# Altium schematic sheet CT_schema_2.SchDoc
size 384 x 228 mm
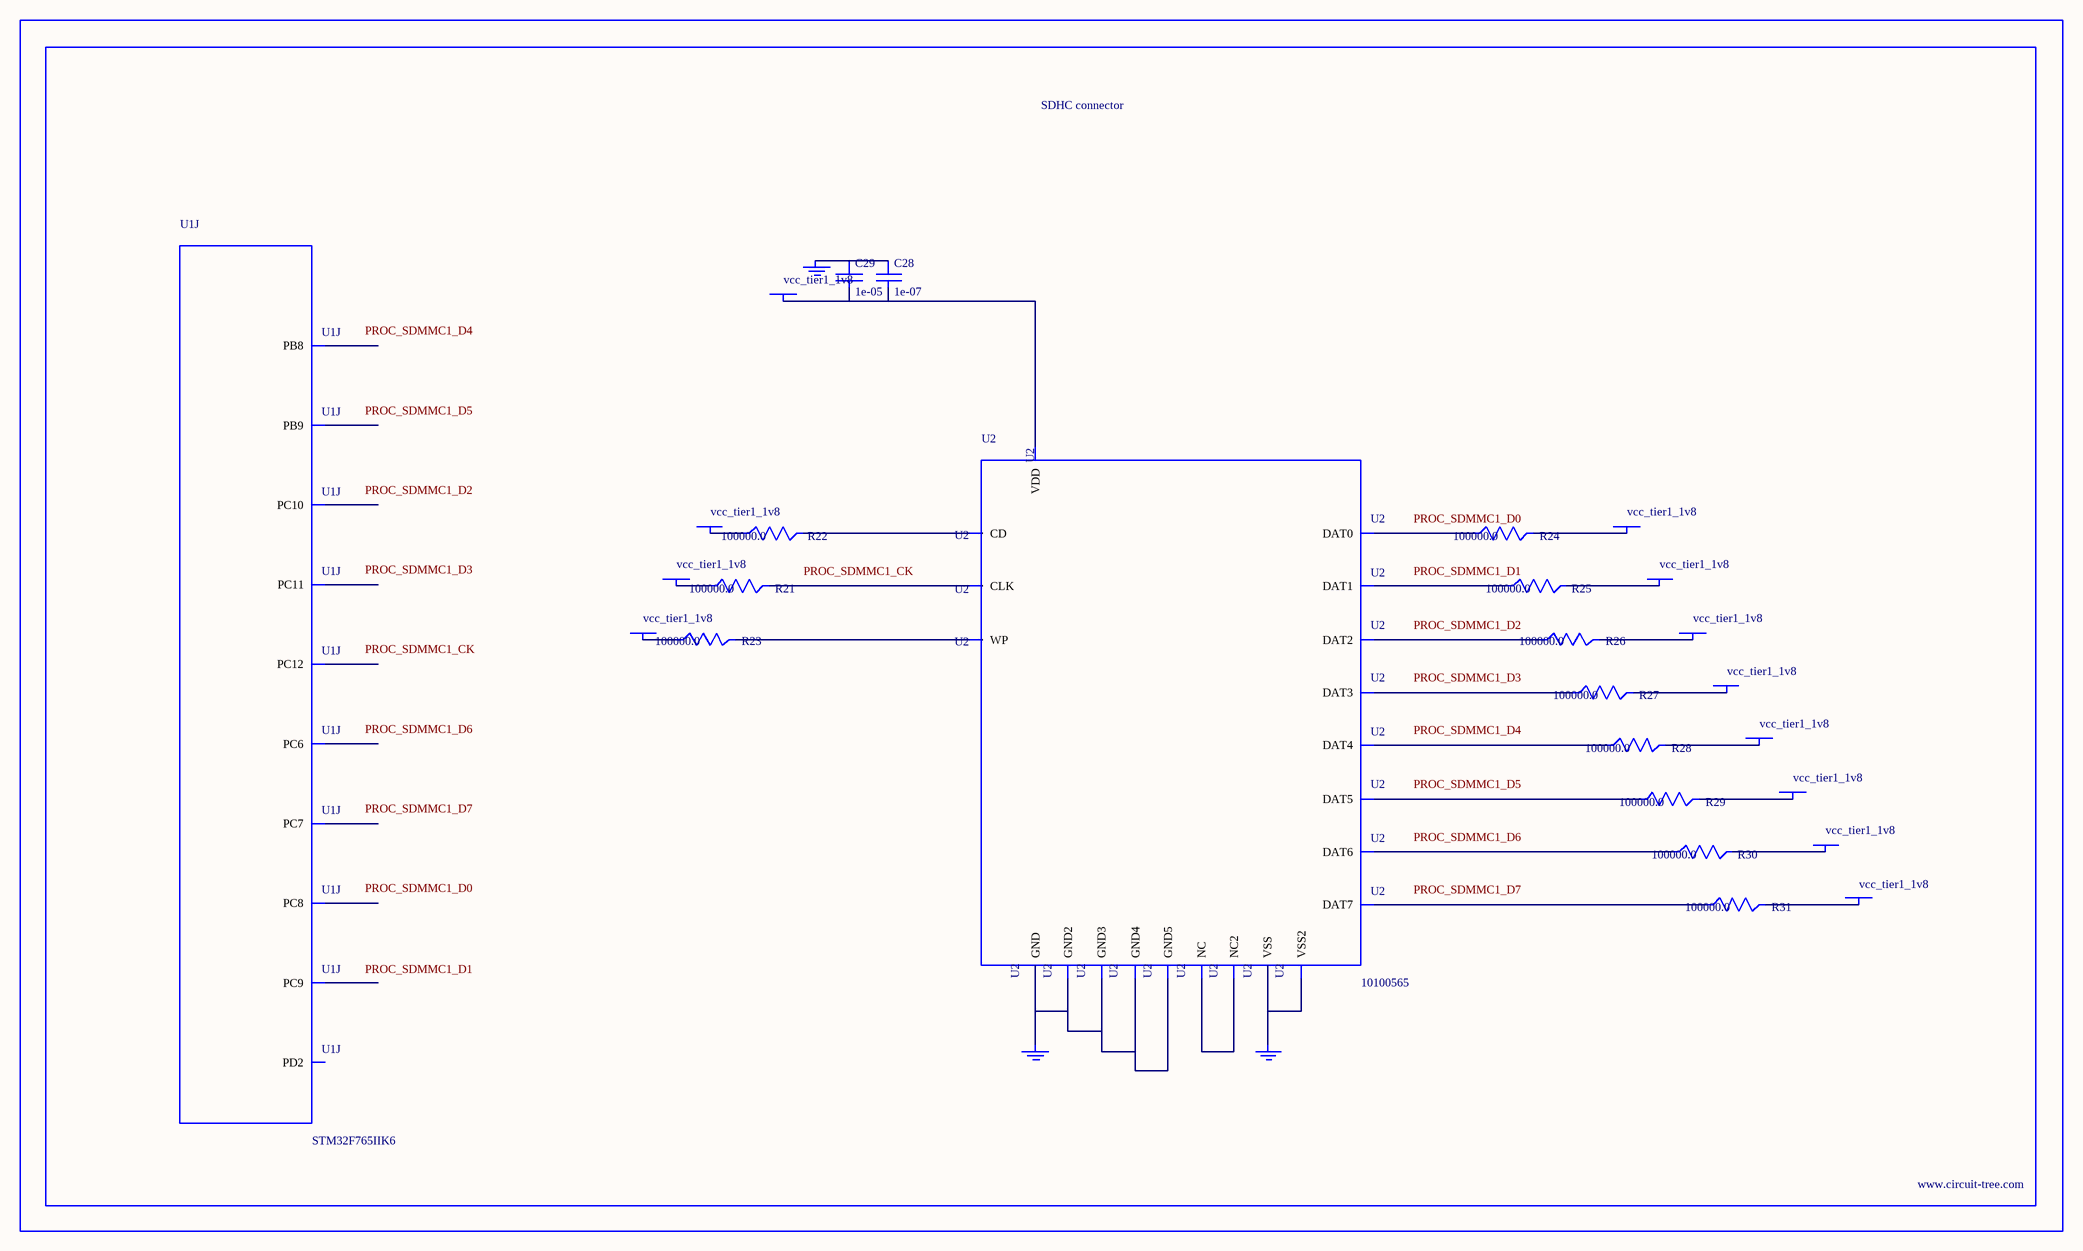
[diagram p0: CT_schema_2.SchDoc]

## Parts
BORDER1  (no value)
C28  1e-07  [C0402]
C29  1e-05  [C0805]
GND_INSTANCE_1_0  (no value)
GND_INSTANCE_1_1  (no value)
GND_INSTANCE_1_2  (no value)
POWER_INSTANCE_1_0  vcc_tier1_1v8
POWER_INSTANCE_1_1  vcc_tier1_1v8
POWER_INSTANCE_1_2  vcc_tier1_1v8
POWER_INSTANCE_1_3  vcc_tier1_1v8
POWER_INSTANCE_1_4  vcc_tier1_1v8
POWER_INSTANCE_1_5  vcc_tier1_1v8
POWER_INSTANCE_1_6  vcc_tier1_1v8
POWER_INSTANCE_1_7  vcc_tier1_1v8
POWER_INSTANCE_1_8  vcc_tier1_1v8
POWER_INSTANCE_1_9  vcc_tier1_1v8
POWER_INSTANCE_1_10  vcc_tier1_1v8
POWER_INSTANCE_1_11  vcc_tier1_1v8
R21  100000.0  [R0603]
R22  100000.0  [R0603]
R23  100000.0  [R0603]
R24  100000.0  [R0603]
R25  100000.0  [R0603]
R26  100000.0  [R0603]
R27  100000.0  [R0603]
R28  100000.0  [R0603]
R29  100000.0  [R0603]
R30  100000.0  [R0603]
R31  100000.0  [R0603]
U1  STM32F765IIK6  [UFBGA176_25]  (part J of 17)
U2  10100565  [10100565]

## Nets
NetC28_1: C28.1 C29.1 GND_INSTANCE_1_0.0(GND)
NetC28_2: C28.2 C29.2 POWER_INSTANCE_1_7.0(PWR) U2.9(VDD)
NetGND_INSTANCE_1_1_0: GND_INSTANCE_1_1.0(GND) U2.6(VSS) U2.10(VSS2)
NetGND_INSTANCE_1_2_0: GND_INSTANCE_1_2.0(GND) U2.12(GND) U2.16(GND2) U2.17(GND3) U2.20(GND4) U2.21(GND5)
NetPOWER_INSTANCE_1_0_0: POWER_INSTANCE_1_0.0(PWR) R23.1
NetPOWER_INSTANCE_1_1_0: POWER_INSTANCE_1_1.0(PWR) R22.1
NetPOWER_INSTANCE_1_2_0: POWER_INSTANCE_1_2.0(PWR) R25.2
NetPOWER_INSTANCE_1_3_0: POWER_INSTANCE_1_3.0(PWR) R24.2
NetPOWER_INSTANCE_1_4_0: POWER_INSTANCE_1_4.0(PWR) R31.2
NetPOWER_INSTANCE_1_5_0: POWER_INSTANCE_1_5.0(PWR) R30.2
NetPOWER_INSTANCE_1_6_0: POWER_INSTANCE_1_6.0(PWR) R21.1
NetPOWER_INSTANCE_1_8_0: POWER_INSTANCE_1_8.0(PWR) R29.2
NetPOWER_INSTANCE_1_9_0: POWER_INSTANCE_1_9.0(PWR) R28.2
NetPOWER_INSTANCE_1_10_0: POWER_INSTANCE_1_10.0(PWR) R27.2
NetPOWER_INSTANCE_1_11_0: POWER_INSTANCE_1_11.0(PWR) R26.2
NetR21_2: R21.2 U2.8(CLK)
NetR22_2: R22.2 U2.2(CD)
NetR23_2: R23.2 U2.1(WP)
NetR24_1: R24.1 U2.4(DAT0)
NetR25_1: R25.1 U2.3(DAT1)
NetR26_1: R26.1 U2.15(DAT2)
NetR27_1: R27.1 U2.14(DAT3)
NetR28_1: R28.1 U2.13(DAT4)
NetR29_1: R29.1 U2.11(DAT5)
NetR30_1: R30.1 U2.7(DAT6)
NetR31_1: R31.1 U2.5(DAT7)
NetU2_18: U2.18(NC) U2.19(NC2)

Not connected (* = marked no-connect by the designer): U1 A5(PB8) A12(PC12) B4(PB9) B13(PC11) B14(PC10) D12(PD2) F14(PC9) G14(PC8) G15(PC7) H15(PC6)

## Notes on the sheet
- Labels drawn without touching a wire or pin: PROC_SDMMC1_CK, PROC_SDMMC1_D0, PROC_SDMMC1_D1, PROC_SDMMC1_D2, PROC_SDMMC1_D3, PROC_SDMMC1_D4, PROC_SDMMC1_D5, PROC_SDMMC1_D6, PROC_SDMMC1_D7

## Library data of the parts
BORDER1 = BORDER_PAGE1
C28 = C0402C104K3RACTU
C29 = C0805C106K8RACTU
GND_INSTANCE_1_0-GND_INSTANCE_1_2 = GND
POWER_INSTANCE_1_0-POWER_INSTANCE_1_11 = PWR
R21-R31 = RC0603JR-07100KL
